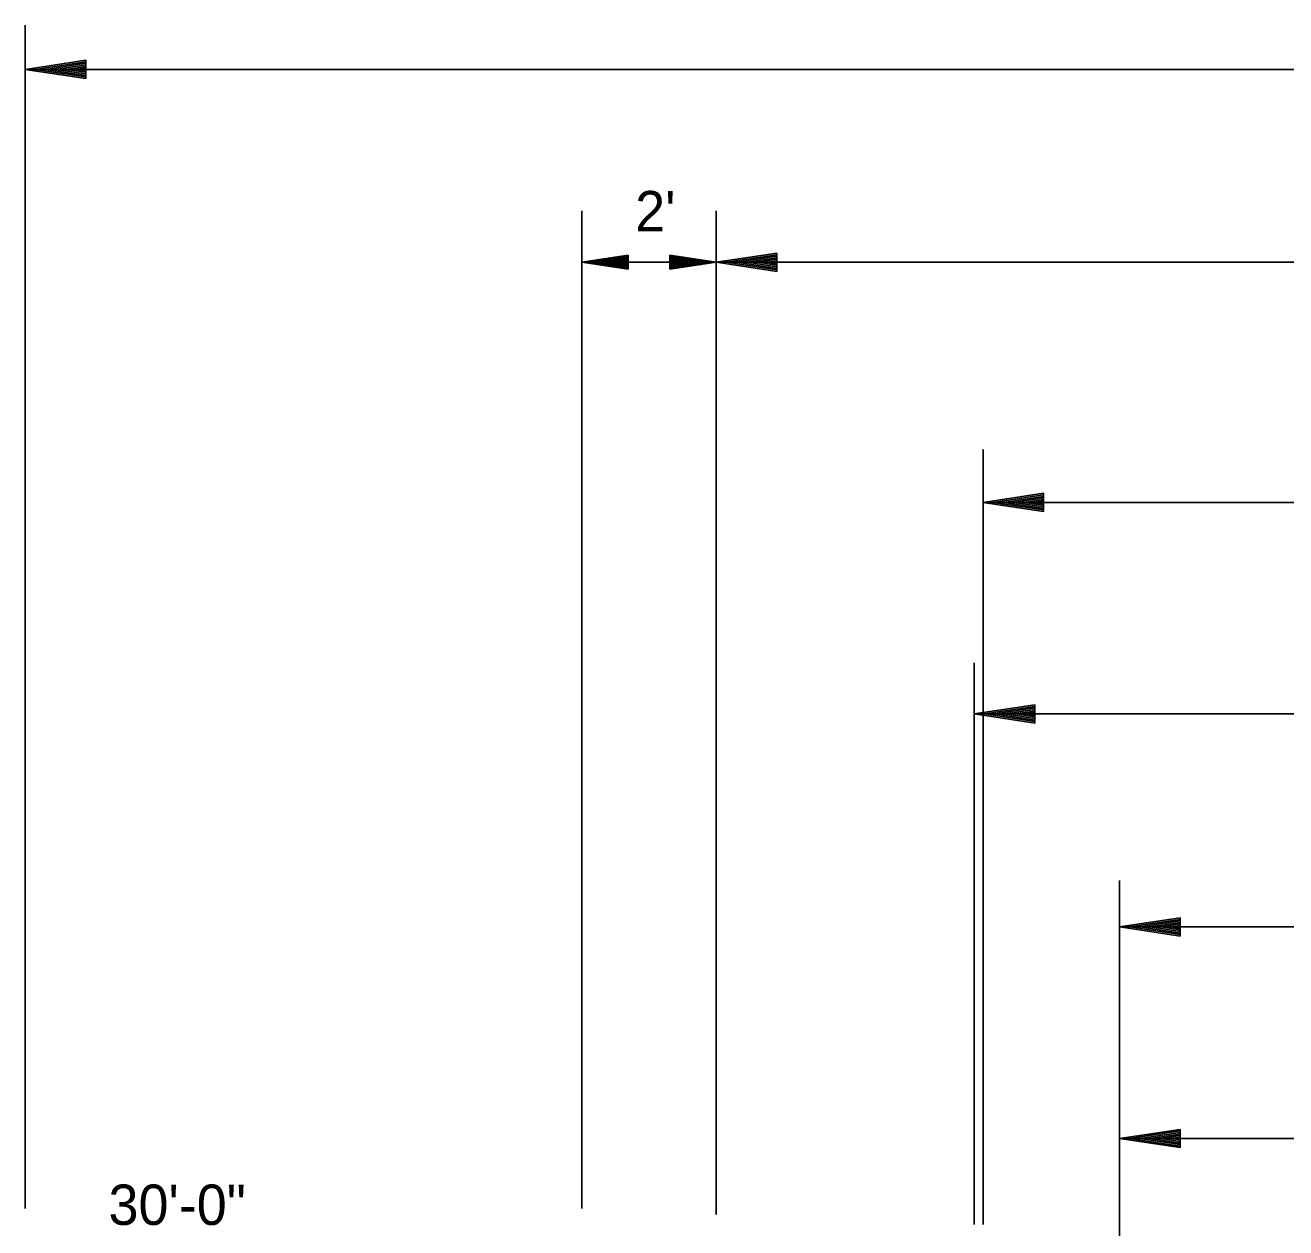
# Model space of a CAD drawing. Extents: x 634177 to 635904, y 289936 to 290970.
# Drawn here: x 635822.4 to 635841.15, y 290618.02 to 290635.9 of the extents above; entities that cross this region are included whole.
import ezdxf

# ---------------------------------------------------------------- set-up
doc = ezdxf.new("R2010")
doc.units = 0
doc.layers.add('Default', color=7, linetype='Continuous')

msp = doc.modelspace()

# ---------------------------------------------------------------- linework, layer by layer
at = {"layer": 'Default'}
for p, q in [((635822.398, 290618.303), (635822.398, 290635.902)), ((635823.298, 290635.381), (635822.398, 290635.246)), ((635823.298, 290635.111), (635823.298, 290635.381)), ((635878.958, 290635.246), (635822.398, 290635.246)), ((635823.298, 290635.111), (635822.398, 290635.246)), ((635823.298, 290635.359), (635822.548, 290635.246)), ((635823.298, 290635.134), (635822.548, 290635.246)), ((635823.298, 290635.336), (635822.703, 290635.246)), ((635823.298, 290635.156), (635822.703, 290635.246)), ((635823.298, 290635.313), (635822.853, 290635.246)), ((635823.298, 290635.18), (635822.853, 290635.246)), ((635823.298, 290635.29), (635823.006, 290635.246)), ((635823.298, 290635.203), (635823.006, 290635.246)), ((635823.298, 290635.268), (635823.156, 290635.246)), ((635823.298, 290635.225), (635823.156, 290635.246)), ((635830.678, 290618.303), (635830.678, 290633.142)), ((635832.678, 290618.212), (635832.678, 290633.142)), ((635831.368, 290632.48), (635830.678, 290632.376)), ((635831.368, 290632.463), (635830.793, 290632.376)), ((635831.368, 290632.445), (635830.912, 290632.376)), ((635831.368, 290632.428), (635831.027, 290632.376)), ((635831.368, 290632.41), (635831.144, 290632.376)), ((635831.368, 290632.393), (635831.259, 290632.376)), ((635831.368, 290632.273), (635831.368, 290632.48)), ((635831.988, 290632.48), (635832.678, 290632.376)), ((635831.988, 290632.48), (635831.988, 290632.273)), ((635831.988, 290632.463), (635832.563, 290632.376)), ((635831.988, 290632.445), (635832.444, 290632.376)), ((635831.988, 290632.428), (635832.329, 290632.376)), ((635831.988, 290632.41), (635832.212, 290632.376)), ((635831.988, 290632.393), (635832.097, 290632.376)), ((635833.578, 290632.511), (635832.678, 290632.376)), ((635833.578, 290632.489), (635832.828, 290632.376)), ((635833.578, 290632.466), (635832.983, 290632.376)), ((635833.578, 290632.443), (635833.133, 290632.376)), ((635833.578, 290632.421), (635833.285, 290632.376)), ((635833.578, 290632.398), (635833.436, 290632.376)), ((635833.578, 290632.241), (635833.578, 290632.511)), ((635830.678, 290632.376), (635832.678, 290632.376)), ((635831.368, 290632.273), (635830.678, 290632.376)), ((635831.368, 290632.29), (635830.793, 290632.376)), ((635831.368, 290632.308), (635830.912, 290632.376)), ((635831.368, 290632.325), (635831.027, 290632.376)), ((635831.368, 290632.343), (635831.144, 290632.376)), ((635831.368, 290632.36), (635831.259, 290632.376)), ((635831.988, 290632.273), (635832.678, 290632.376)), ((635831.988, 290632.343), (635832.212, 290632.376)), ((635831.988, 290632.308), (635832.444, 290632.376)), ((635831.988, 290632.29), (635832.563, 290632.376)), ((635831.988, 290632.325), (635832.329, 290632.376)), ((635831.988, 290632.36), (635832.097, 290632.376)), ((635868.678, 290632.376), (635832.678, 290632.376)), ((635833.578, 290632.241), (635832.678, 290632.376)), ((635833.578, 290632.264), (635832.828, 290632.376)), ((635833.578, 290632.286), (635832.983, 290632.376)), ((635833.578, 290632.31), (635833.133, 290632.376)), ((635833.578, 290632.333), (635833.285, 290632.376)), ((635833.578, 290632.355), (635833.436, 290632.376)), ((635836.649, 290619.495), (635836.649, 290629.591)), ((635837.549, 290628.94), (635836.649, 290628.805)), ((635837.549, 290628.918), (635836.8, 290628.805)), ((635837.549, 290628.895), (635836.955, 290628.805)), ((635837.549, 290628.872), (635837.104, 290628.805)), ((635837.549, 290628.849), (635837.257, 290628.805)), ((635837.549, 290628.827), (635837.407, 290628.805)), ((635837.549, 290628.67), (635837.549, 290628.94)), ((635864.678, 290628.805), (635836.649, 290628.805)), ((635837.549, 290628.67), (635836.649, 290628.805)), ((635837.549, 290628.693), (635836.8, 290628.805)), ((635837.549, 290628.715), (635836.955, 290628.805)), ((635837.549, 290628.739), (635837.104, 290628.805)), ((635837.549, 290628.762), (635837.257, 290628.805)), ((635837.549, 290628.784), (635837.407, 290628.805)), ((635836.517, 290618.066), (635836.517, 290626.419)), ((635837.417, 290625.793), (635836.517, 290625.658)), ((635864.678, 290625.658), (635836.517, 290625.658)), ((635837.417, 290625.523), (635836.517, 290625.658)), ((635837.417, 290625.771), (635836.667, 290625.658)), ((635837.417, 290625.546), (635836.667, 290625.658)), ((635837.417, 290625.748), (635836.822, 290625.658)), ((635837.417, 290625.568), (635836.822, 290625.658)), ((635837.417, 290625.725), (635836.972, 290625.658)), ((635837.417, 290625.592), (635836.972, 290625.658)), ((635837.417, 290625.702), (635837.125, 290625.658)), ((635837.417, 290625.615), (635837.125, 290625.658)), ((635837.417, 290625.68), (635837.275, 290625.658)), ((635837.417, 290625.637), (635837.275, 290625.658)), ((635837.417, 290625.523), (635837.417, 290625.793)), ((635838.678, 290612.837), (635838.678, 290623.179)), ((635839.578, 290622.625), (635838.678, 290622.49)), ((635838.678, 290622.49), (635850.518, 290622.49)), ((635839.578, 290622.355), (635838.678, 290622.49)), ((635839.578, 290622.603), (635838.828, 290622.49)), ((635839.578, 290622.378), (635838.828, 290622.49)), ((635839.578, 290622.58), (635838.983, 290622.49)), ((635839.578, 290622.4), (635838.983, 290622.49)), ((635839.578, 290622.557), (635839.133, 290622.49)), ((635839.578, 290622.424), (635839.133, 290622.49)), ((635839.578, 290622.535), (635839.285, 290622.49)), ((635839.578, 290622.447), (635839.285, 290622.49)), ((635839.578, 290622.512), (635839.436, 290622.49)), ((635839.578, 290622.469), (635839.436, 290622.49)), ((635839.578, 290622.355), (635839.578, 290622.625)), ((635836.649, 290618.066), (635836.649, 290619.495)), ((635839.578, 290619.478), (635838.678, 290619.343)), ((635839.578, 290619.456), (635838.828, 290619.343)), ((635839.578, 290619.208), (635839.578, 290619.478)), ((635839.578, 290619.208), (635838.678, 290619.343)), ((635838.678, 290619.343), (635850.518, 290619.343)), ((635839.578, 290619.231), (635838.828, 290619.343)), ((635839.578, 290619.433), (635838.983, 290619.343)), ((635839.578, 290619.253), (635838.983, 290619.343)), ((635839.578, 290619.41), (635839.133, 290619.343)), ((635839.578, 290619.277), (635839.133, 290619.343)), ((635839.578, 290619.388), (635839.285, 290619.343)), ((635839.578, 290619.3), (635839.285, 290619.343)), ((635839.578, 290619.365), (635839.436, 290619.343)), ((635839.578, 290619.322), (635839.436, 290619.343))]:
    msp.add_line(p, q, dxfattribs=at)

# ---------------------------------------------------------------- texts
for s, p in [("2'", (635831.472, 290632.837)), ('30\'-0"', (635823.637, 290618.059))]:
    msp.add_text(s, height=0.6, dxfattribs=at).set_placement(p)

doc.saveas('drawing.dxf')
